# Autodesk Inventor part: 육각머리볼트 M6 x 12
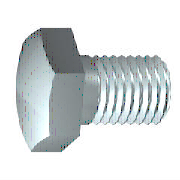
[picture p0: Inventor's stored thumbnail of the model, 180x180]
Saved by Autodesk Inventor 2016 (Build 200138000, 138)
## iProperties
IsCustomPart: 1
Created: 2012-02
Part Number: 육각머리볼트 M6 x 12
Material: 스테인리스강
Description: 6각 머리 나사
Document SubType Name: Modeling
Standard: ISO 4017
Designer: mdu-01
Standard Revision: Third edition 1999-08-15
Standards Organization: ISO
Language: ko-KR
Size Designation: M6 x 12
Categories: <MemberInstance><Categories><Category DisplayName="조임쇠" InternalName="e4da775c-781d-43d5-af7c-5136215cf5a6" Mnemonic="FSTN"><Category DisplayName="볼트" InternalN
Density: 7.75 g/cm^3
Appearance: 반광택
Author: mdu-01
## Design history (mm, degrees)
sketch "스케치1"
  geometry: L1 (0, 4.44)-(0, 3); L2 (1.15, 3)-(12, 3); L3 (12, 3)-(12, 0); L4 (12, 0)-(-0.5, 0); L5 (-3, 0)-(14.5, 0) reference; L6 (-0.5, 0)-(-0.5, 4.44); L7 (-0.5, 4.44)-(0, 4.44); L8 (1.15, 3)-(0.536, 3); L9 (0.536, 3)-(0, 3); L10 (0, -0.888)-(0, 5.328) reference
  constraints: 16 end point, 2 collinear, 2 perpendicular, 1 parallel
  dimensions: "d0" = 12 distance between parallel lines of L3 L1 (= NLG); "d1" = 10.85 distance from line of L2.start L3 (= GEL); "d2" = 6 diameter of L2 L4 (= GD); "d9" = 0.5001 distance between parallel lines of L6 L1 (computed from SD); "d10" = 8.88 diameter of L7 L4 (= SD2); "d13" = 0.61355 distance of L2.start L8.end (computed from GAL); "d14" = 6 diameter of L9 L4 (= BDM)
revolve "본체" sketch "스케치1" stored, may be unused: angle "d12" = 90 deg
sketch "스케치2"
  geometry: L1 (0, 5.774)-(5, 2.887); L2 (5, 2.887)-(5, -2.887); L3 (5, -2.887)-(0, -5.774); L4 (0, -5.774)-(-5, -2.887); L5 (-5, -2.887)-(-5, 2.887); L6 (-5, 2.887)-(0, 5.774); 2 further points
  constraints: 12 end point, 1 coincident, 1 vertical, 11 other
  dimensions: "d11" = 10 distance between parallel lines of L5 L2 (= SW)
extrude "머리" join sketch "스케치2" distance "d3" = 3.5 (= KOH - SD); taper "d4" = 0 deg
sketch "스케치4"
  geometry: L1 (-4, 5)-(-4, 5.774); L2 (-4, 5.774)-(-3.554, 5.774); L3 (-3.554, 5.774)-(-4, 5); L4 (-4.7, 0)-(0.2, 0) reference; L5 (-0.5, 5.774)-(-4, 5.774) reference; L6 (-4, 2.887)-(-4, 5.774) reference
  constraints: 6 end point, 2 collinear, 1 perpendicular, 1 vertical
  dimensions: "d5" = 30 deg angle of L3 L1 (= ANG1); "d19" = 10 diameter of L1.start L4 (= SW0)
revolve "모따기1" sketch "스케치4" stored, may be unused: angle "d21" = 90 deg
workplane "Work Plane1"
body "Solid1"
feature "스레드" dims "d15" = 10.85 (= GEL), "d16" = 0
chamfer "모따기2" distance "d6" = 0.61345 (= -0.5 x SPD + 0.5 x GD); stored, may be unused: second distance "d7" = 0.61355 (computed from GUL), angle "d55" = 45 deg
other parameters: "NLG" = 12 [user parameter; used in 1 equation term], "GD" = 6 (= NND) [user parameter; used in 2 equation terms], "BDM" = 6 (= NND) [user parameter; used in 1 equation term], "KOH" = 4 [user parameter; used in 1 equation term], "GEL" = 10.85 [user parameter; used in 2 equation terms], "SW" = 10 [user parameter; used in 2 equation terms], "SW0" = 10 (= SW) [user parameter; used in 1 equation term], "SPD" = 4.7731 (= NND - 1.2269 x PTC) [user parameter; used in 1 equation term], "SD2" = 8.88 [user parameter; used in 2 equation terms], "SD" = 0.5 [user parameter; used in 2 equation terms], "ANG1" = 30 deg [user parameter; used in 1 equation term], "GAL" = 0.61345 (= 0.61345 x PTC) [user parameter; used in 1 equation term], "GUL" = 0.61345 (= 0.61345 x PTC) [user parameter; used in 1 equation term], "d8" = 0, "RR" = 0.25 [user parameter], "d57" = 0, "d58" = 0, "GD1" = 4.7731 (= THREADDIA - 1.2269 x PTC) [user parameter], "THREADDIA" = 6 [user parameter; used in 1 equation term], "SDH" = 8.88 (= SD2) [user parameter], "SDHG" = 3 [user parameter], "TOA" = 30 deg [user parameter], "PTC" = 1 [user parameter; used in 5 equation terms], "NND" = 6 [user parameter; used in 3 equation terms], "E0" = 11.55 [user parameter]
